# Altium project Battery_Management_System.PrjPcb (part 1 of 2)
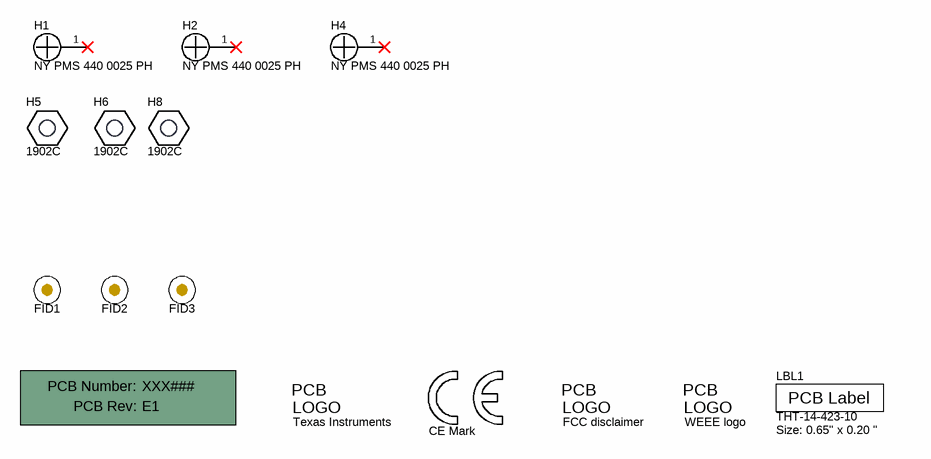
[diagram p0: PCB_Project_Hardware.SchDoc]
CopyrightYear: 2018; PCB_Layout: Who did the Layout?; PCB_Rev: E1; PRJ_Customer: Public Release; PRJ_Engineer: Enter name of project lead; PRJ_Number: XXX###; PRJ_Title: Change in menu Project|Project Options|Parameters; SCH_Rev: E1; TechSupport: http://www.ti.com/support; TID: N/A
8 sheets, 426 parts. Net scope: flat (ports and power ports of the same name join across sheets).
Board file: BMS Layout.PcbDoc
Sheets:
  PCB_Project_Hardware.SchDoc
  Block_Diagram.SchDoc
  Batt_Stack_Control (NMOS).SchDoc
  Power Tree.SchDoc
  MCU_ADC.SchDoc
  Balancer.SchDoc
  Temp Sensing.SchDoc
  Monitor.SchDoc

## Sheet PCB_Project_Hardware.SchDoc
size 431 x 279 mm; Date: Not shown in title block; ApprovedBy: Not shown in title block; CheckedBy: Not shown in title block; Author: Not shown in title block; CompanyName: Not shown in title block; Engineer: Not shown in title block; Organization: Not shown in title block; Address1: Not shown in title block; Address2: Not shown in title block; Address3: Not shown in title block; Address4: Not shown in title block; DocumentNumber: 3; Revision: Use project parameter SCH_Rev; SheetNumber: 1; SheetTotal: 8; PageSetup: Record=PageOptions¦CenterHorizontal=True¦CenterVertical=True¦PrintScale=1.00¦XCorrection=1.00¦YCorrection=1.00¦PrintKind=0¦BorderSize=5000000¦LeftOffset=0¦BottomOffset=0¦Orientation=2¦PaperLength=1000¦PaperWidth=1000¦Scale=100¦PaperSource=15¦PrintQuality=600¦MediaType=1¦DitherType=10¦PaperKind=Letter¦PrintScaleMode=1

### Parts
!PCB1  Printed Circuit Board  (value not drawn)  (mechanical)
FID1  Fiducial  [Fiducial10-20]  (value not drawn)
FID2  Fiducial  [Fiducial10-20]  (value not drawn)
FID3  Fiducial  [Fiducial10-20]  (value not drawn)
H1  NY PMS 440 0025 PH  [NY PMS 440 0025 PH]
H2  NY PMS 440 0025 PH  [NY PMS 440 0025 PH]
H4  NY PMS 440 0025 PH  [NY PMS 440 0025 PH]
H5  1902C  [Keystone_1902C]
H6  1902C  [Keystone_1902C]
H8  1902C  [Keystone_1902C]
LBL1  THT-14-423-10  Note: Size: 0.65" x 0.20 "  [Label_650x200]
Logo1  CE Mark  [CE_Mark_5mm]  (no BOM)
Logo2  Texas Instruments  [TI_Symbol_Overlay_Small]  (no BOM)
Logo3  FCC disclaimer  [FCC_disclaimer]  (no BOM)
Logo4  WEEE logo  [WEEE_Minimum]  (no BOM)

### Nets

Not connected (* = marked no-connect by the designer): H1 1*; H2 1*; H4 1*

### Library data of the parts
!PCB1 = CMP-0003618-2: Manufacturer: Any; PartNumber: XXX###
FID1-FID3 = CMP-0077181-1: Fiducial mark.  There is nothing to buy or mount.
H1 H2 H4 = CMP-0003617-1: Machine Screw, Round, #4-40 x 1/4, Nylon, Philips panhead; Manufacturer: B&F Fastener Supply; CompType: Hardware
H5 H6 H8 = CMP-0003610-1: Standoff, Hex, 0.5"L #4-40 Nylon; Manufacturer: Keystone; CompType: Hardware
LBL1 = CMP-0003625-1: Thermal Transfer Printable Labels, 0.650" W x 0.200" H - 10,000 per roll; Manufacturer: Brady; CompType: Label
Logo1 = CMP-0074844-1: SymbolCreator: a0412235
Logo2 = CMP-0074838-1: Texas Instrument Corporate Signature; SymbolCreator: a0412235; Lib Reference: TI_Logo; Library Reference: Logo
Logo3 = CMP-0074847-1: FCC_disclaimer; Library Reference: Logo
Logo4 = CMP-0074769-1

## Sheet Block_Diagram.SchDoc
size 431 x 279 mm; Date: Not shown in title block; ApprovedBy: Not shown in title block; CheckedBy: Not shown in title block; Author: Not shown in title block; CompanyName: Not shown in title block; Engineer: Not shown in title block; Organization: Not shown in title block; Address1: Not shown in title block; Address2: Not shown in title block; Address3: Not shown in title block; Address4: Not shown in title block; DocumentNumber: 2; Revision: Use project parameter SCH_Rev; SheetNumber: 2; SheetTotal: 8; PageSetup: Record=PageOptions¦CenterHorizontal=True¦CenterVertical=True¦PrintScale=1.00¦XCorrection=1.00¦YCorrection=1.00¦PrintKind=0¦BorderSize=5000000¦LeftOffset=0¦BottomOffset=0¦Orientation=2¦PaperLength=1000¦PaperWidth=1000¦Scale=100¦PaperSource=15¦PrintQuality=600¦MediaType=1¦DitherType=10¦PaperKind=Letter¦PrintScaleMode=1
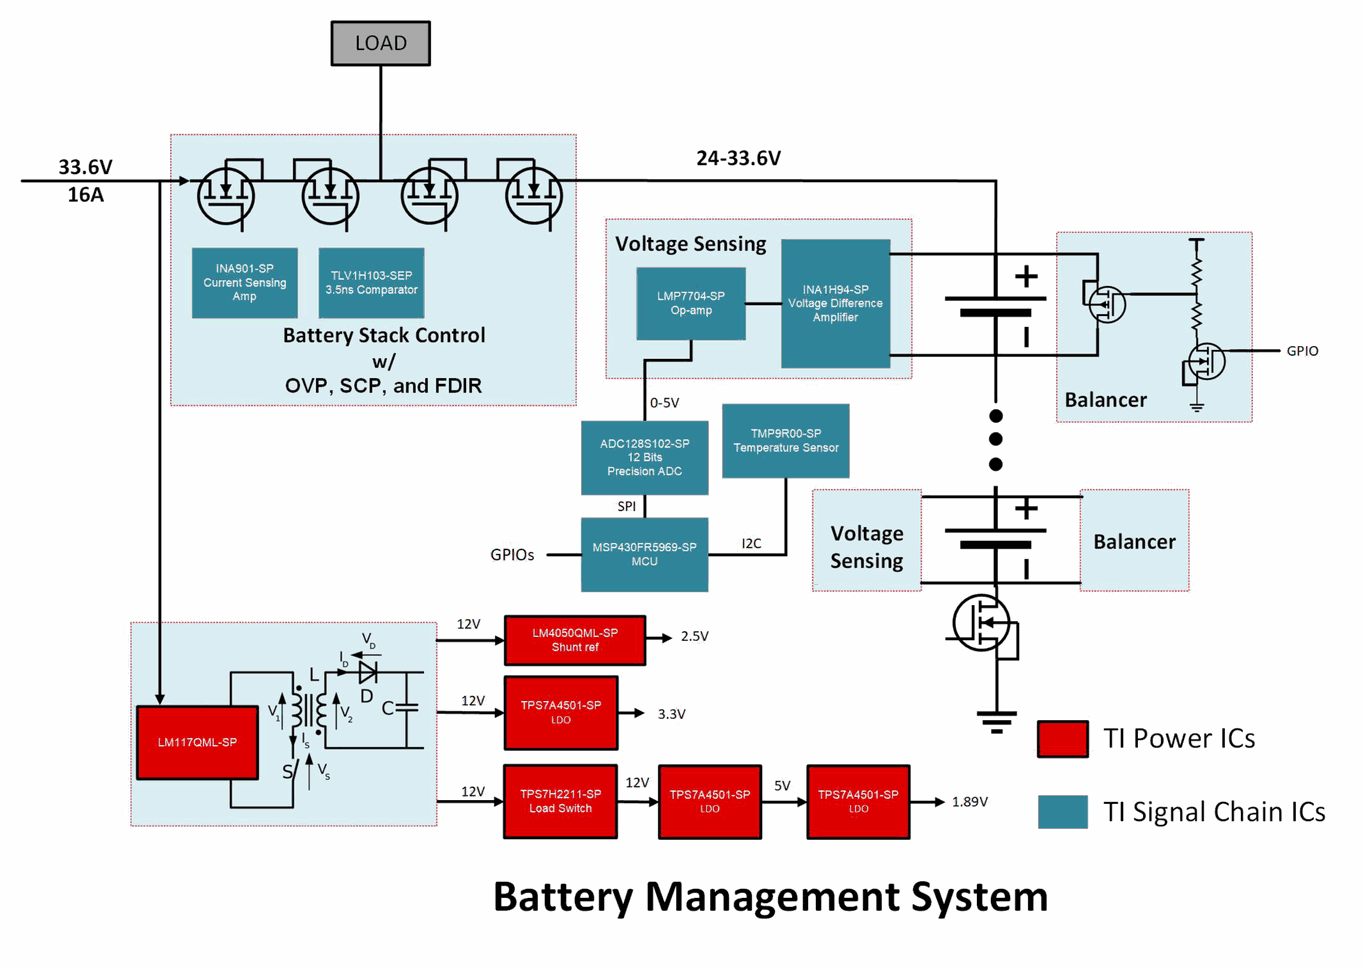
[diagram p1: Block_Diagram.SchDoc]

## Sheet Batt_Stack_Control (NMOS).SchDoc
size A2; Date: Not shown in title block; ApprovedBy: Not shown in title block; CheckedBy: Not shown in title block; Author: Not shown in title block; CompanyName: Not shown in title block; Engineer: Not shown in title block; Organization: Not shown in title block; Address1: Not shown in title block; Address2: Not shown in title block; Address3: Not shown in title block; Address4: Not shown in title block; DocumentNumber: 1; Revision: Use project parameter SCH_Rev; SheetNumber: 3; SheetTotal: 8; PageSetup: Record=PageOptions¦CenterHorizontal=True¦CenterVertical=True¦PrintScale=0.69¦XCorrection=1.00¦YCorrection=1.00¦PrintKind=0¦BorderSize=5000000¦LeftOffset=0¦BottomOffset=0¦Orientation=2¦PaperLength=1000¦PaperWidth=1000¦Scale=100¦PaperSource=15¦PrintQuality=600¦MediaType=1¦DitherType=10¦PaperKind=Letter¦PrintScaleMode=1
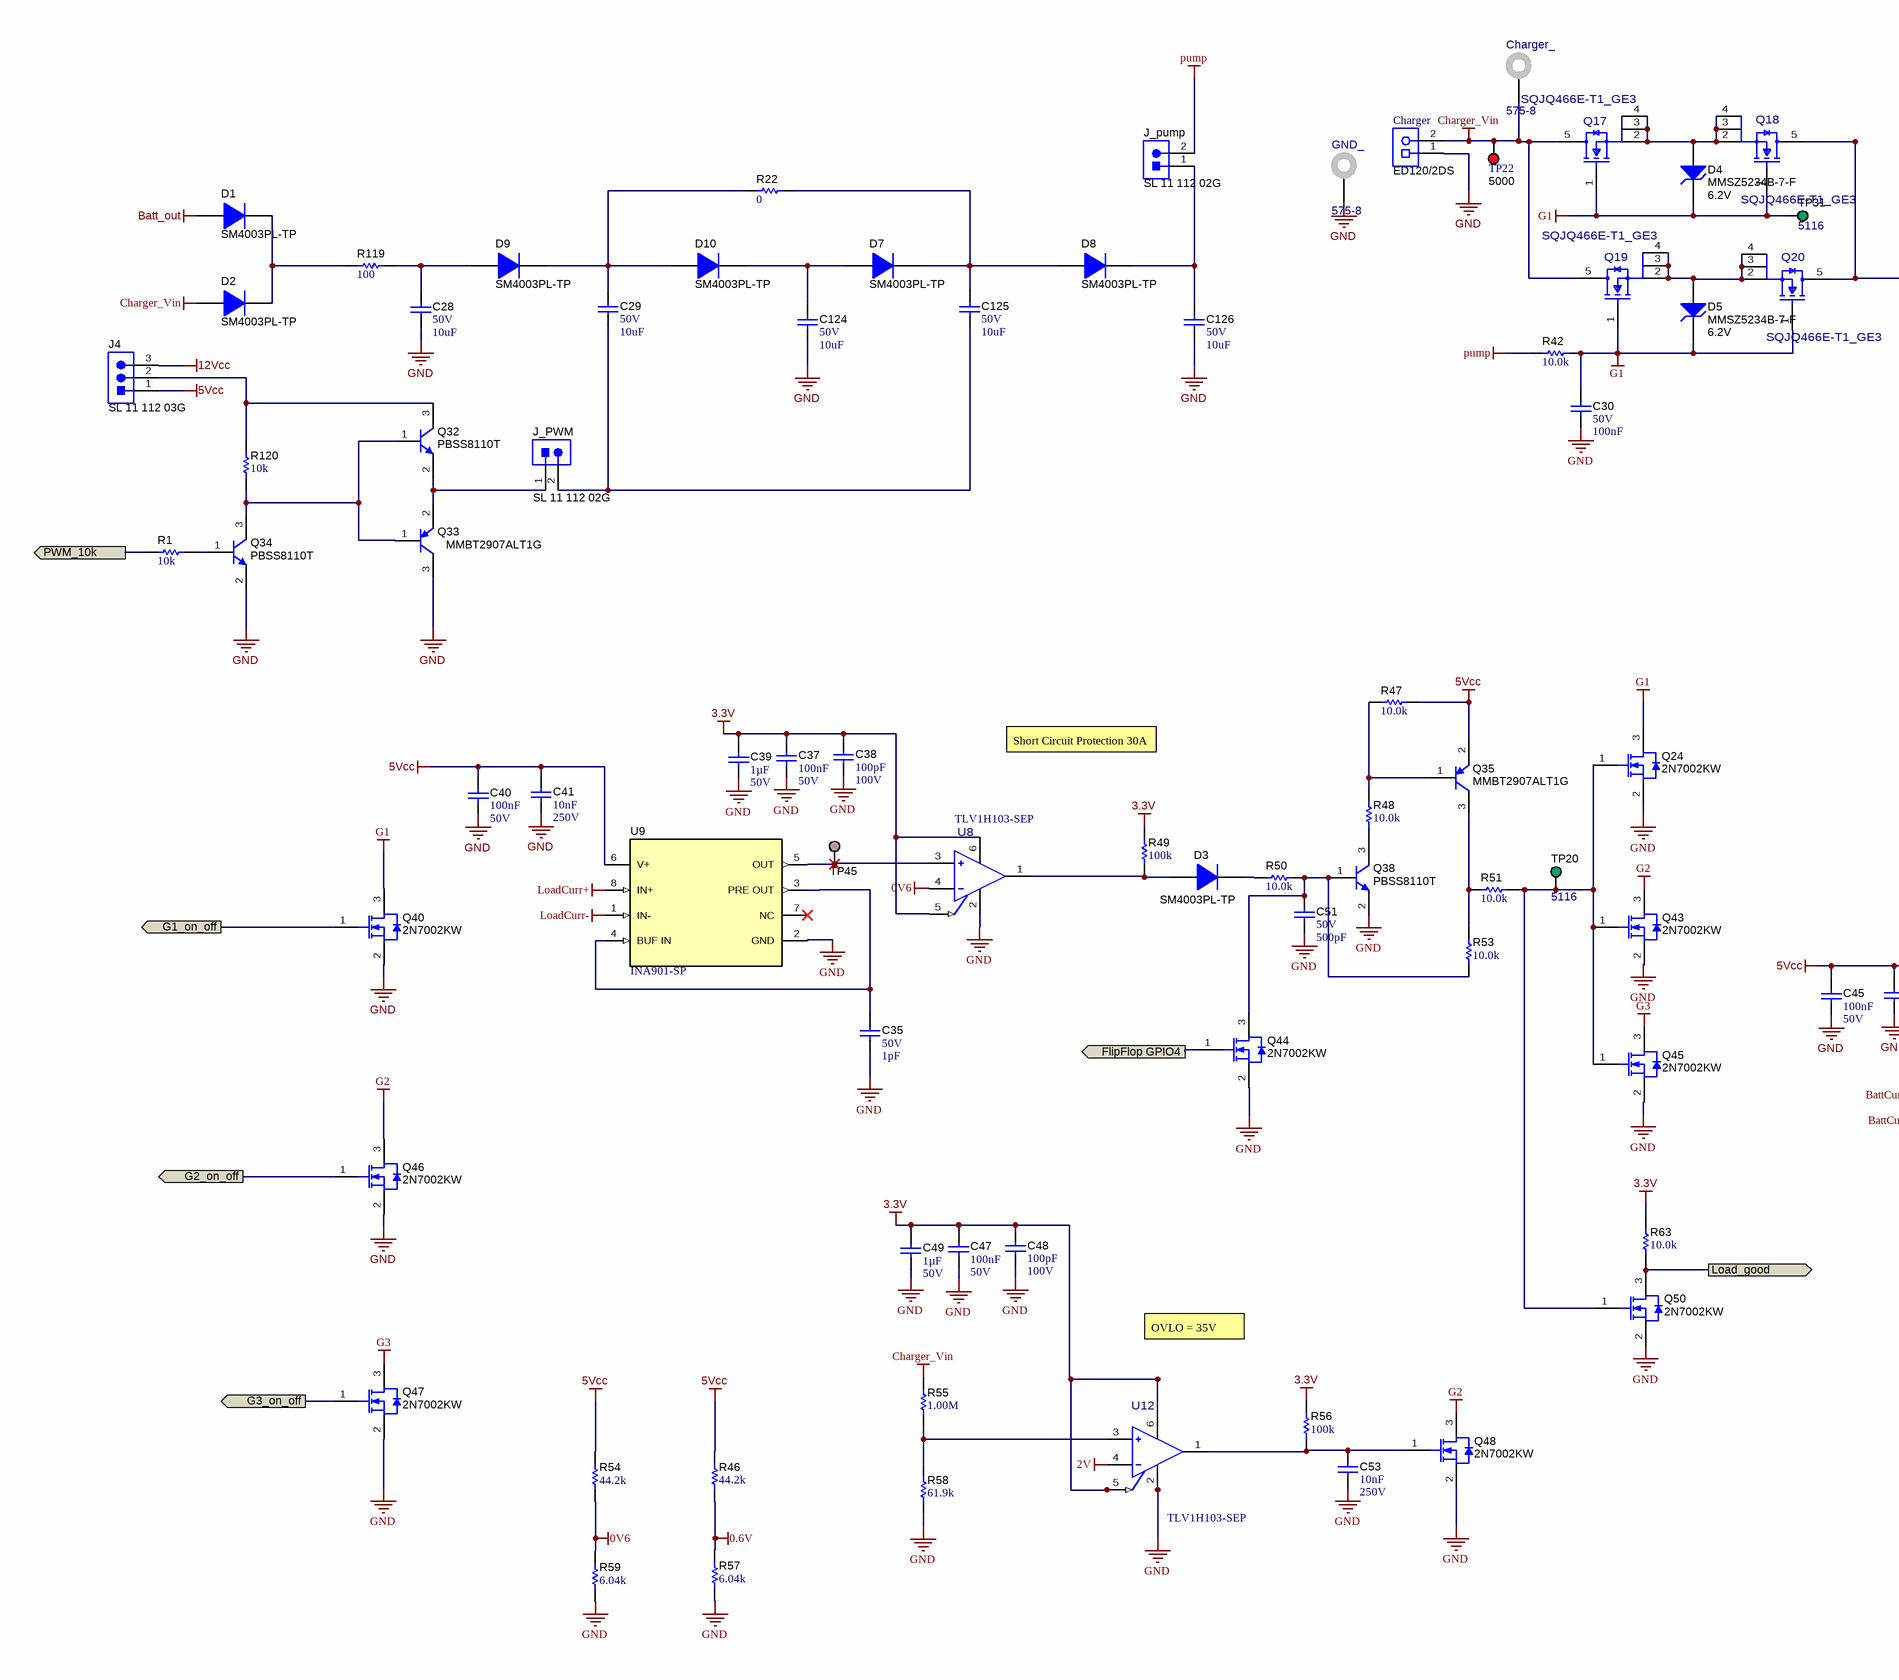
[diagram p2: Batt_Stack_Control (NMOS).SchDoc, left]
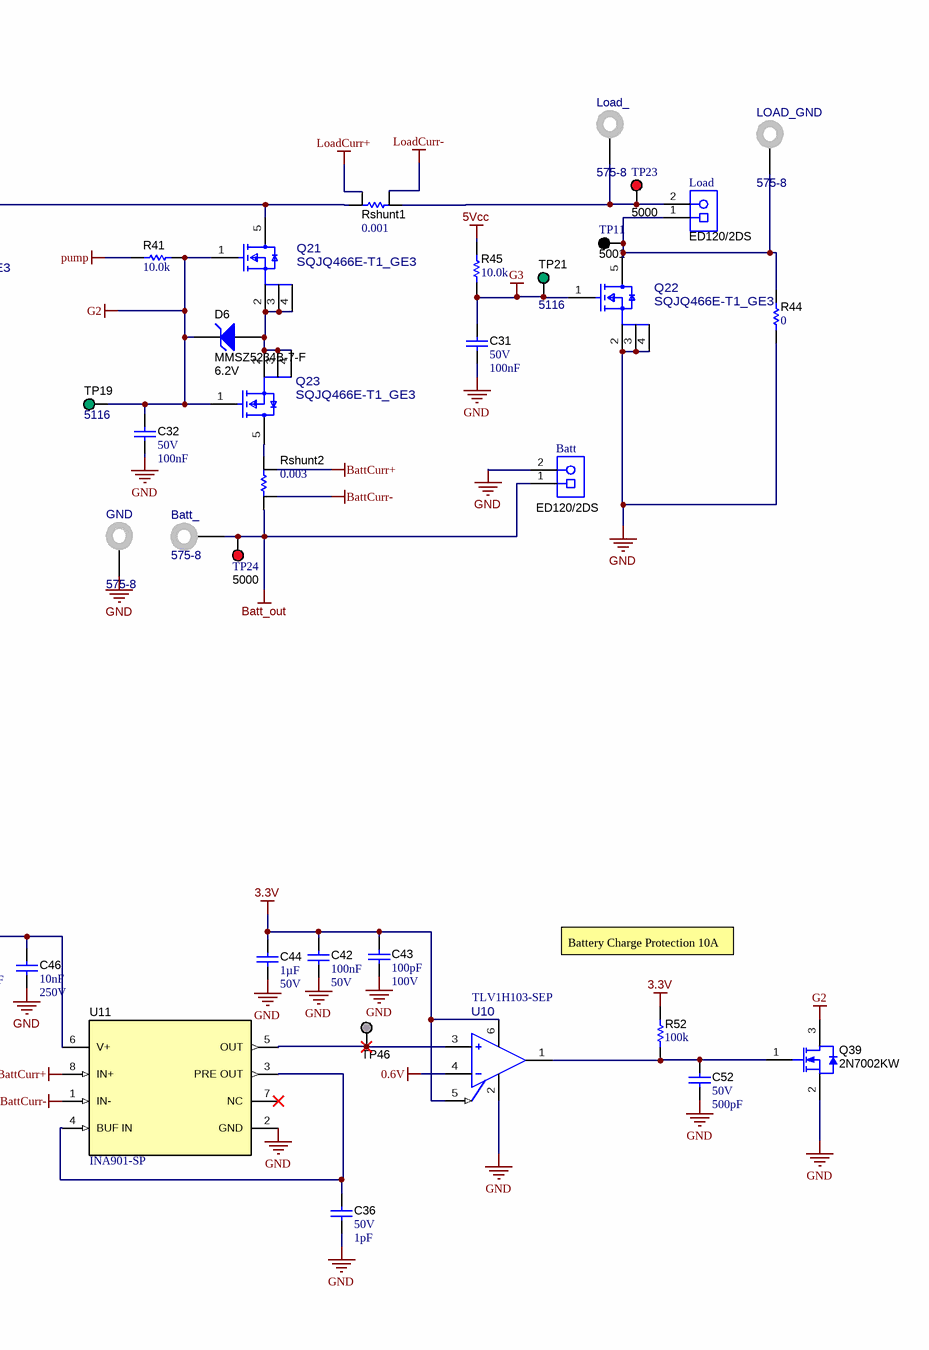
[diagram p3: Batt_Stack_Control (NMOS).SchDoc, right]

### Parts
Batt  ED120/2DS  [On-Shore_ED120_2DS]
Batt_  575-8  [Keystone575-8]
C28  VDC_V: 50V  ValueDisplayed: 10uF  [1210_280]  (hidden comment: CGA6P3X7S1H106K250AB)
C29  VDC_V: 50V  ValueDisplayed: 10uF  [1210_280]  (hidden comment: CGA6P3X7S1H106K250AB)
C30  VDC_V: 50V  Cap_F: 100nF  [0805_HV]  (hidden comment: 08055C104KAT2A)
C31  VDC_V: 50V  Cap_F: 100nF  [0805_HV]  (hidden comment: 08055C104KAT2A)
C32  VDC_V: 50V  Cap_F: 100nF  [0805_HV]  (hidden comment: 08055C104KAT2A)
C35  VDC_V: 50V  ValueDisplayed: 1pF  [0805_HV]  (hidden comment: CC0805CRNP09BN1R0)
C36  VDC_V: 50V  ValueDisplayed: 1pF  [0805_HV]  (hidden comment: CC0805CRNP09BN1R0)
C37  Cap_F: 100nF  VDC_V: 50V  [0805_HV]  (hidden comment: GCM21BR71H104KA37K)
C38  Cap_F: 100pF  VDC_V: 100V  [0805_HV]  (hidden comment: C0805C101J1RACTU)
C39  Cap_F: 1µF  VDC_V: 50V  [0805_HV]  (hidden comment: GCJ21BR71H105MA01L)
C40  Cap_F: 100nF  VDC_V: 50V  [0805_HV]  (hidden comment: GCM21BR71H104KA37K)
C41  Cap_F: 10nF  VDC_V: 250V  [0805_HV]  (hidden comment: QMK212B7103KG-T)
C42  Cap_F: 100nF  VDC_V: 50V  [0805_HV]  (hidden comment: GCM21BR71H104KA37K)
C43  Cap_F: 100pF  VDC_V: 100V  [0805_HV]  (hidden comment: C0805C101J1RACTU)
C44  Cap_F: 1µF  VDC_V: 50V  [0805_HV]  (hidden comment: GCJ21BR71H105MA01L)
C45  Cap_F: 100nF  VDC_V: 50V  [0805_HV]  (hidden comment: GCM21BR71H104KA37K)
C46  Cap_F: 10nF  VDC_V: 250V  [0805_HV]  (hidden comment: QMK212B7103KG-T)
C47  Cap_F: 100nF  VDC_V: 50V  [0805_HV]  (hidden comment: GCM21BR71H104KA37K)
C48  Cap_F: 100pF  VDC_V: 100V  [0805_HV]  (hidden comment: C0805C101J1RACTU)
C49  Cap_F: 1µF  VDC_V: 50V  [0805_HV]  (hidden comment: GCJ21BR71H105MA01L)
C51  VDC_V: 50V  ValueDisplayed: 500pF  [0805_HV]  (hidden comment: 08055A501GAT2A)
C52  VDC_V: 50V  ValueDisplayed: 500pF  [0805_HV]  (hidden comment: 08055A501GAT2A)
C53  Cap_F: 10nF  VDC_V: 250V  [0805_HV]  (hidden comment: QMK212B7103KG-T)
C124  VDC_V: 50V  ValueDisplayed: 10uF  [1210_280]  (hidden comment: CGA6P3X7S1H106K250AB)
C125  VDC_V: 50V  ValueDisplayed: 10uF  [1210_280]  (hidden comment: CGA6P3X7S1H106K250AB)
C126  VDC_V: 50V  ValueDisplayed: 10uF  [1210_280]  (hidden comment: CGA6P3X7S1H106K250AB)
Charger  ED120/2DS  [On-Shore_ED120_2DS]
Charger_  575-8  [Keystone575-8]
D1  SM4003PL-TP  [SOD-123FL]
D2  SM4003PL-TP  [SOD-123FL]
D3  SM4003PL-TP  [SOD-123FL]
D4  MMSZ5234B-7-F  value 6.2V  [SOD-123]
D5  MMSZ5234B-7-F  value 6.2V  [SOD-123]
D6  MMSZ5234B-7-F  value 6.2V  [SOD-123]
D7  SM4003PL-TP  [SOD-123FL]
D8  SM4003PL-TP  [SOD-123FL]
D9  SM4003PL-TP  [SOD-123FL]
D10  SM4003PL-TP  [SOD-123FL]
GND  575-8  [Keystone575-8]
GND_  575-8  [Keystone575-8]
J4  SL 11 112 03G  [Fischer_SL-11-112-03G]
J_pump  SL 11 112 02G  [Fischer_SL-11-112-02G]
J_PWM  SL 11 112 02G  [Fischer_SL-11-112-02G]
Load  ED120/2DS  [On-Shore_ED120_2DS]
Load_  575-8  [Keystone575-8]
LOAD_GND  575-8  [Keystone575-8]
Q17  SQJQ466E-T1_GE3  [FP-SQJQ466E-T1_GE3_PowerPAK 8 x 8L-MFG]
Q18  SQJQ466E-T1_GE3  [FP-SQJQ466E-T1_GE3_PowerPAK 8 x 8L-MFG]
Q19  SQJQ466E-T1_GE3  [FP-SQJQ466E-T1_GE3_PowerPAK 8 x 8L-MFG]
Q20  SQJQ466E-T1_GE3  [FP-SQJQ466E-T1_GE3_PowerPAK 8 x 8L-MFG]
Q21  SQJQ466E-T1_GE3  [FP-SQJQ466E-T1_GE3_PowerPAK 8 x 8L-MFG]
Q22  SQJQ466E-T1_GE3  [FP-SQJQ466E-T1_GE3_PowerPAK 8 x 8L-MFG]
Q23  SQJQ466E-T1_GE3  [FP-SQJQ466E-T1_GE3_PowerPAK 8 x 8L-MFG]
Q24  2N7002KW  [SOT-323]
Q32  PBSS8110T  [SOT-23]
Q33  MMBT2907ALT1G  [SOT-23]
Q34  PBSS8110T  [SOT-23]
Q35  MMBT2907ALT1G  [SOT-23]
Q38  PBSS8110T  [SOT-23]
Q39  2N7002KW  [SOT-323]
Q40  2N7002KW  [SOT-323]
Q43  2N7002KW  [SOT-323]
Q44  2N7002KW  [SOT-323]
Q45  2N7002KW  [SOT-323]
Q46  2N7002KW  [SOT-323]
Q47  2N7002KW  [SOT-323]
Q48  2N7002KW  [SOT-323]
Q50  2N7002KW  [SOT-323]
R1  ValueDisplayed: 10k  [0805_HV]  (hidden comment: ERJ-6GEYJ103V)
R22  ValueDisplayed: 0  [0805_HV]  (hidden comment: MCR10EZHJ000)
R41  ValueDisplayed: 10.0k  [0805_HV]  (hidden comment: CRCW080510K0FKEA)
R42  ValueDisplayed: 10.0k  [0805_HV]  (hidden comment: CRCW080510K0FKEA)
R44  ValueDisplayed: 0  [2512]  (hidden comment: 3522ZR)
R45  ValueDisplayed: 10.0k  [0805_HV]  (hidden comment: CRCW080510K0FKEA)
R46  ValueDisplayed: 44.2k  [0805_HV]  (hidden comment: RT0805BRD0744K2L)
R47  ValueDisplayed: 10.0k  [0805_HV]  (hidden comment: CRCW080510K0FKEA)
R48  ValueDisplayed: 10.0k  [0805_HV]  (hidden comment: CRCW080510K0FKEA)
R49  ValueDisplayed: 100k  [0805_HV]  (hidden comment: RG2012P-104-B-T5)
R50  ValueDisplayed: 10.0k  [0805_HV]  (hidden comment: CRCW080510K0FKEA)
R51  ValueDisplayed: 10.0k  [0805_HV]  (hidden comment: CRCW080510K0FKEA)
R52  ValueDisplayed: 100k  [0805_HV]  (hidden comment: RG2012P-104-B-T5)
R53  ValueDisplayed: 10.0k  [0805_HV]  (hidden comment: CRCW080510K0FKEA)
R54  ValueDisplayed: 44.2k  [0805_HV]  (hidden comment: RT0805BRD0744K2L)
R55  ValueDisplayed: 1.00M  [1206]  (hidden comment: RC1206FR-071ML)
R56  ValueDisplayed: 100k  [0805_HV]  (hidden comment: RG2012P-104-B-T5)
R57  ValueDisplayed: 6.04k  [0805_HV]  (hidden comment: RT0805BRD076K04L)
R58  ValueDisplayed: 61.9k  [1206]  (hidden comment: ERJ-8ENF6192V)
R59  ValueDisplayed: 6.04k  [0805_HV]  (hidden comment: RT0805BRD076K04L)
R63  ValueDisplayed: 10.0k  [0805_HV]  (hidden comment: CRCW080510K0FKEA)
R119  ValueDisplayed: 100  [0805_HV]  (hidden comment: CRCW0805100RJNEA)
R120  ValueDisplayed: 10k  [0805_HV]  (hidden comment: ERJ-6GEYJ103V)
Rshunt1  ValueDisplayed: 0.001  [WSL3637_0.001]  (hidden comment: WSL36371L000FEA)
Rshunt2  ValueDisplayed: 0.003  [WSL3637_0_002]  (hidden comment: WSL36373L000FEA)
TP11  5001  [Keystone5001]
TP19  5116  [Keystone_5116]
TP20  5116  [Keystone_5116]
TP21  5116  [Keystone_5116]
TP22  5000  [Keystone5000]
TP23  5000  [Keystone5000]
TP24  5000  [Keystone5000]
TP31  5116  [Keystone_5116]
TP45  TP_SM_1MM  [TP_SM_1MM]  (value not drawn)
TP46  TP_SM_1MM  [TP_SM_1MM]  (value not drawn)
U8  PartNumber: TLV1H103-SEP  [DBV0006A-MFG]  (hidden comment: TLV1H103MDBVTSEP)
U9  PartNumber: INA901-SP  [HKX0008A_Custom_A]  (hidden comment: INA901HKX/EM)
U10  PartNumber: TLV1H103-SEP  [DBV0006A-MFG]  (hidden comment: TLV1H103MDBVTSEP)
U11  PartNumber: INA901-SP  [HKX0008A_Custom_A]  (hidden comment: INA901HKX/EM)
U12  PartNumber: TLV1H103-SEP  [DBV0006A-MFG]  (hidden comment: TLV1H103MDBVTSEP)

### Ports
FlipFlop GPIO4 (out), G1_on_off (out), G2_on_off (out), G3_on_off (out), Load_good (out), PWM_10k (out)

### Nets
0.6V: R46.1 R57.2 U10.4(IN-)
0V6: R54.1 R59.2 U8.4(IN-)
2V: U12.4(IN-)
3.3V: C37.1 C38.1 C39.1 C42.1 C43.1 C44.1 C47.1 C48.1 C49.1 R49.2 R52.2 R56.2 R63.2 U8.5(~{LE}/HYST) U8.6(VCC) U10.5(~{LE}/HYST) U10.6(VCC) U12.5(~{LE}/HYST) U12.6(VCC)
5Vcc: C40.1 C41.1 C45.1 C46.1 J4.1 Q35.2(E) R45.2 R46.2 R47.2 R54.2 U9.6(V+) U11.6(V+)
12Vcc: J4.3
Batt_out: Batt.1 Batt_.1 D1.2(A) Rshunt2.2 TP24.1
BattCurr+: Rshunt2.3 U11.8(IN+)
BattCurr-: Rshunt2.4 U11.1(IN-)
Charger_Vin: Charger.2 Charger_.1 D2.2(A) Q17.5(D) Q19.5(D) R55.2 TP22.1
G1: C30.1 D4.1(K) D5.1(K) Q17.1(G) Q18.1(G) Q19.1(G) Q20.1(G) Q24.3(D) Q40.3(D) R42.2 TP31.1
G2: C32.1 D6.1(K) Q21.1(G) Q23.1(G) Q39.3(D) Q43.3(D) Q46.3(D) Q48.3(D) R41.2 TP19.1
G3: C31.1 Q22.1(G) Q45.3(D) Q47.3(D) R45.1 TP21.1
GND: Batt.2 C28.2 C30.2 C31.2 C32.2 C35.2 C36.2 C37.2 C38.2 C39.2 C40.2 C41.2 C42.2 C43.2 C44.2 C45.2 C46.2 C47.2 C48.2 C49.2 C51.2 C52.2 C53.2 C124.2 C126.2 Charger.1 GND.1 GND_.1 Q22.2(S) Q22.3(S) Q22.4(S) Q24.2(S) Q33.3(C) Q34.2(E) Q38.2(E) Q39.2(S) Q40.2(S) Q43.2(S) Q44.2(S) Q45.2(S) Q46.2(S) Q47.2(S) Q48.2(S) Q50.2(S) R44.1 R57.1 R58.1 R59.1 U8.2(VEE) U9.2(GND) U10.2(VEE) U11.2(GND) U12.2(VEE)
LoadCurr+: Rshunt1.3 U9.8(IN+)
LoadCurr-: Rshunt1.4 U9.1(IN-)
pump: J_pump.2 R41.1 R42.1
FlipFlop GPIO4: Q44.1(G) ; port FlipFlop GPIO4
G1_on_off: Q40.1(G) ; port G1_on_off
G2_on_off: Q46.1(G) ; port G2_on_off
G3_on_off: Q47.1(G) ; port G3_on_off
Load_good: Q50.3(D) R63.1 ; port Load_good
PWM_10k: R1.2 ; port PWM_10k
NetC28_1: C28.1 D9.2(A) R119.2
NetC29_1: C29.1 D9.1(K) D10.2(A) R22.2
NetC29_2: C29.2 C125.2 J_PWM.2
NetC35_1: C35.1 U9.3(PRE_OUT) U9.4(BUF_IN)
NetC36_1: C36.1 U11.3(PRE_OUT) U11.4(BUF_IN)
NetC51_1: C51.1 Q38.1(B) Q44.3(D) R50.2 R53.1
NetC52_1: C52.1 Q39.1(G) R52.1 U10.1(OUT)
NetC53_1: C53.1 Q48.1(G) R56.1 U12.1(OUT)
NetC124_1: C124.1 D7.2(A) D10.1(K)
NetC125_1: C125.1 D7.1(K) D8.2(A) R22.1
NetC126_1: C126.1 D8.1(K) J_pump.1
NetD1_1: D1.1(K) D2.1(K) R119.1
NetD3_1: D3.1(K) R50.1
NetD3_2: D3.2(A) R49.1 U8.1(OUT)
NetD4_2: D4.2(A) Q17.2(S) Q17.3(S) Q17.4(S) Q18.2(S) Q18.3(S) Q18.4(S)
NetD5_2: D5.2(A) Q19.2(S) Q19.3(S) Q19.4(S) Q20.2(S) Q20.3(S) Q20.4(S)
NetD6_2: D6.2(A) Q21.2(S) Q21.3(S) Q21.4(S) Q23.2(S) Q23.3(S) Q23.4(S)
NetJ4_2: J4.2 Q32.3(C) R120.2
NetJ_PWM_1: J_PWM.1 Q32.2(E) Q33.2(E)
NetLoad_1: Load.1 LOAD_GND.1 Q22.5(D) R44.2 TP11.1
NetLoad_2: Load.2 Load_.1 Rshunt1.2 TP23.1
NetQ18_5: Q18.5(D) Q20.5(D) Q21.5(D) Rshunt1.1
NetQ23_5: Q23.5(D) Rshunt2.1
NetQ24_1: Q24.1(G) Q43.1(G) Q45.1(G) Q50.1(G) R51.2 TP20.1
NetQ32_1: Q32.1(B) Q33.1(B) Q34.3(C) R120.1
NetQ34_1: Q34.1(B) R1.1
NetQ35_1: Q35.1(B) R47.1 R48.2
NetQ35_3: Q35.3(C) R51.1 R53.2
NetQ38_3: Q38.3(C) R48.1
NetR55_1: R55.1 R58.2 U12.3(IN+)
NetTP45_1: TP45.1 U8.3(IN+) U9.5(OUT)
NetTP46_1: TP46.1 U10.3(IN+) U11.5(OUT)

Not connected (* = marked no-connect by the designer): U9 7(NC)*; U11 7(NC)*

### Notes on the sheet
- Short Circuit Protection 30A
- Battery Charge Protection 10A
- OVLO = 35V

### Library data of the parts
Batt Charger Load = CMP-0074910-1: Terminal Block, 5.08 mm, 2x1, Brass, TH; Manufacturer: On-Shore Technology; Cert_VDE: Y; CNHeader: False; Current_A: 15A; Green_Lifecycle: Not Set; Shrouded: N; Gender: Female; Green_REACh: Incomplete; Voltage_V: 300V; Row_Count: 1; Pitch_mm: 5.08; CT: True
Batt_ Charger_ GND GND_ Load_ LOAD_GND = CMP-0055166-1: Standard Banana Jack, Uninsulated, 8.9mm; Manufacturer: Keystone; CT: TRUE; Green_REACh: Passed; CNHeader: FALSE; Green_Lifecycle: Active
C28 C29 C124-C126 = CMP-0009164-1: CAP, CERM, 10 uF, 50 V, +/- 10%, X7S, AEC-Q200 Grade 1, 1210; Manufacturer: TDK; TaMin_C: -55°C; ESR_ohm: 2.827m; Polarized: N; SizeAreaWB_mm2: 14.7; Value1: 0.002827 ohm; U/M: EA; Value: 10uF; TaMax_C: 125°C; SizeZ_mm: 2.8; SizeX_mm: 3.2; SizeY_mm: 2.5; SizeArea_mm2: 8; AEC Qualified: Y; Cap_F: 10µF; IRMS_A: 4.3729A; AEC Grade: 1; AEC Category: Q200
C30-C32 = CMP-0007632-2: CAP, CERM, 0.1 uF, 50 V, +/- 10%, X7R, 0805; Manufacturer: AVX; TaMin_C: -55°C; ESR_ohm: 0.024; Polarized: N; SizeAreaWB_mm2: 6.75; Value1: 0.024 ohm; U/M: EA; Value: 0.1uF; TaMax_C: 125°C; SizeZ_mm: 1.45; SizeX_mm: 2; SizeY_mm: 1.25; Cap_Case: 0805; SizeArea_mm2: 2.5; AEC Category: Q200
C35 C36 = CMP-0007900-2: CAP, CERM, 1 pF, 50 V, +/- 25%, C0G/NP0, 0805; Manufacturer: Yageo America; TaMin_C: -55°C; Polarized: N; SizeAreaWB_mm2: 6.75; Value1: Unknown; U/M: EA; Value: 1pF; TaMax_C: 125°C; SizeZ_mm: 1.45; SizeX_mm: 2; SizeY_mm: 1.25; Cap_Case: 0805; SizeArea_mm2: 2.5; AEC Category: Q200
C37 C40 C42 C45 C47 = CMP-0008021-2: CAP, CERM, 0.1 uF, 50 V, +/- 10%, X7R, AEC-Q200 Grade 1, 0805; Manufacturer: MuRata; TaMin_C: -55°C; Polarized: N; SizeAreaWB_mm2: 6.75; Value1: Unknown; U/M: EA; Value: 0.1uF; TaMax_C: 125°C; SizeZ_mm: 1.45; SizeX_mm: 2; SizeY_mm: 1.25; Cap_Case: 0805; SizeArea_mm2: 2.5; AEC Qualified: Y; AEC Grade: 1; AEC Category: Q200
C38 C43 C48 = CMP-0007706-2: CAP, CERM, 100 pF, 100 V, +/- 5%, X7R, 0805; Manufacturer: Kemet; TaMin_C: -55°C; Polarized: N; SizeAreaWB_mm2: 6.75; Value1: Unknown; U/M: EA; Value: 100pF; TaMax_C: 125°C; SizeZ_mm: 1.45; SizeX_mm: 2; SizeY_mm: 1.25; Cap_Case: 0805; SizeArea_mm2: 2.5; AEC Category: Q200
C39 C44 C49 = CMP-0080480-1: CAP, CERM, 1 µF, 50 V,+/- 20%, X7R, AEC-Q200 Grade 1, 0805; Manufacturer: MuRata; TaMin_C: -55°C; Polarized: N; SizeAreaWB_mm2: 6.75; U/M: EA; Value: 1uF; TaMax_C: 125°C; SizeZ_mm: 1.45; SizeX_mm: 2; SizeY_mm: 1.25; Cap_Case: 0805; SizeArea_mm2: 2.5; AEC Qualified: Y; AEC Grade: 1; AEC Category: Q200
C41 C46 C53 = CMP-0008408-2: CAP, CERM, 0.01 uF, 250 V, +/- 10%, X7R, 0805; Manufacturer: Taiyo Yuden; TaMin_C: -55°C; Polarized: N; SizeAreaWB_mm2: 6.75; Value1: Unknown; U/M: EA; Value: 0.01uF; TaMax_C: 125°C; SizeZ_mm: 1.45; SizeX_mm: 2; SizeY_mm: 1.25; Cap_Case: 0805; SizeArea_mm2: 2.5; AEC Category: Q200
C51 C52 = CMP-0080090-1: CAP, CERM, 500 pF, 50 V,+/- 2%, C0G/NP0, 0805; Manufacturer: AVX; SizeAreaWB_mm2: 6.75; SizeArea_mm2: 2.5; AEC Qualified: N; AEC Category: Q200; Value: 500pF; TaMax_C: 125°C; SizeZ_mm: 1.45; TaMin_C: -55°C; SizeY_mm: 1.25; U/M: EA; SizeX_mm: 2; Cap_Case: 0805
D1-D3 D7-D10 = CMP-0077083-2: Diode, Standard Recovery Rectifier, 200 V, 1 A, SOD-123FL; Manufacturer: Micro Commercial Components; Green_Lifecycle: Not Set; AEC Category: Q101; SizeArea_mm2: 5.94; Vr_V: 200V; SizeAreaWB_mm2: 12.19; SizeY_mm: 1.65; AEC Qualified: N; SizeZ_mm: 0.98; SizeX_mm: 3.6; Green_REACh: Incomplete; Vf_V: 1.1V; TJmax_C: 175°C; Value: 200V; Value1: 1A
D4-D6 = CMP-0005805-3: Diode, Zener, 6.2 V, 500 mW, SOD-123; Manufacturer: Diodes Inc.; SizeY_mm: 1.7; AEC Category: Q101; SizeAreaWB_mm2: 13.095; SizeZ_mm: 1.35; SizeArea_mm2: 6.545; RJA_CperW: 350; Power_W: 500mW; Value1: 0.5W; SizeX_mm: 3.85
J4 = CMP-0075048-1: Header, 2.54mm, 3x1, Gold, TH; Manufacturer: Fischer Elektronik; CT: False; CNHeader: True
J_pump J_PWM = CMP-0075049-1: Header, 2.54mm, 2x1, Gold, TH; Manufacturer: Fischer Elektronik; CT: False; CNHeader: True
Q17-Q23 = CMP-0093493-1: N-Channel 60 V 200A (Tc) 150W (Tc) Surface Mount PowerPAK® 8 x 8; Manufacturer: Vishay; AEC Qualified: Yes; QgTyp_nC: 135nC @ 10V; Rdson45_ohm: 1.7m; SizeZ_mm: 2.03mm; VdsMax_V: 1.2V; Vgs_V: 20V; ChMode: False; Pulse Drain Current: 500A; Rthja Max: 50°C/W; TJmax_C: +175°C; Typ Forward Diode Voltage: 0.82V; Input Capacitace At Vds: 8170pF @ 25V; Turn Off Delay Time: 47ns; Standoff Height: 0mm; Turn On Delay Time: 24ns; Number Of N Channels: 1; Drain To Source Breakdown Voltage: 60V; Threshold Vgs Min: 2.5V; Threshold Vgs Max: 3.5V; AEC Grade: Grade 0; Transconductance: 140S
Q24 Q39 Q40 Q43-Q48 Q50 = CMP-0000774-1: MOSFET, N-CH, 60 V, 0.31 A, SOT-323; Alternate Manufacturer: None; Manufacturer: Fairchild Semiconductor; SizeZ_mm: 1.1; ChType: N; Value1: 1; VdsMax_V: 60V; SizeX_mm: 2.2; Vgs_V: 2.1V; Value: 60V; Rdson45_ohm: 1.6; SizeArea_mm2: 4.84; AEC Category: Q101; IdsMax_A: 3.1dA; SizeAreaWB_mm2: 10.24; U/M: EA
Q32 Q34 Q38 = CMP-0000451-1: Transistor, NPN, 100 V, 1 A, SOT-23; Manufacturer: NXP Semiconductor; TaMax_C: 150°C; Value2: 500; Value1: 1 A; Vcesat1_V: 40mV; SizeX_mm: 2.5; SizeY_mm: 3; TaMin_C: -65°C; IcRated_A: 1A; CompType: BJT; SizeZ_mm: 1.1; Value: 100 V; SizeArea_mm2: 7.5; NPN: 1; Vceo_V: 100V; PNP: 0; AEC Category: Q101; SizeAreaWB_mm2: 14; U/M: EA
Q33 Q35 = CMP-0000344-1: Transistor, PNP, 60 V, 0.6 A, SOT-23; Manufacturer: ON Semiconductor; TaMax_C: 150°C; Value1: 0.6 A; Vcesat1_V: 1.6V; SizeX_mm: 2.5; SizeY_mm: 3; TaMin_C: -55°C; IcRated_A: 600mA; CompType: BJT; SizeZ_mm: 1.1; Value: 60 V; SizeArea_mm2: 7.5; NPN: 0; Vceo_V: 60V; PNP: 1; AEC Category: Q101; SizeAreaWB_mm2: 14; U/M: EA
R1 R120 = CMP-0020620-3: RES, 10 k, 5%, 0.125 W, AEC-Q200 Grade 0, 0805; Manufacturer: Panasonic; Power_W: 125mW; TempCo: 200 ppm/C; Value_Code: 10k0; Value: 10k; EIA_Code: E24; SizeX_mm: 2; SizeY_mm: 1.25; SizeZ_mm: 1.45; Value2: 0.125W; SizeArea_mm2: 2.5; AEC Qualified: Y; VDC_V: 150V; AEC Category: Q200; AEC Grade: 0; SizeAreaWB_mm2: 6.75
R22 = CMP-0020801-3: RES, 0, 5%, 0.125 W, 0805; Manufacturer: Rohm; SizeX_mm: 2; Value_Code: 0000; MFG_Status: TI_Obsolete; U/M: EA; SizeZ_mm: 1.45; Power_W: 125mW; Value: 0; TempCo: 400 ppm/C; SizeY_mm: 1.25; EIA_Code: E24; Value2: 0.125W; AEC Category: Q200; VDC_V: 150V; SizeArea_mm2: 2.5
R41 R42 R45 R47 R48 R50 R51 R53 R63 = CMP-0020842-3: RES, 10.0 k, 1%, 0.125 W, AEC-Q200 Grade 0, 0805; Manufacturer: Vishay-Dale; Power_W: 125mW; TempCo: 100 ppm/C; Value_Code: 10k0; Value: 10.0k; EIA_Code: E96; Res_ohm: 10k; SizeX_mm: 2; SizeY_mm: 1.25; SizeZ_mm: 1.45; Value2: 0.125W; SizeArea_mm2: 2.5; AEC Qualified: Y; VDC_V: 150V; AEC Category: Q200; AEC Grade: 0
R44 = CMP-0086260-1: RES, 0, 3 W, 2512; Manufacturer: TE Connectivity; SizeAreaWB_mm2: 43.16; Value: 0; SizeArea_mm2: 20.16; EIA_Code: E24; SizeZ_mm: 0.71; AEC Category: Q200; SizeX_mm: 6.3; Value_Code: 0000; Power_W: 3W; Tolerance_%: 0%; SizeY_mm: 3.2; AEC Qualified: N
R46 R54 = CMP-0020087-2: RES, 44.2 k, 0.1%, 0.125 W, 0805; Manufacturer: Yageo America; Power_W: 125mW; TempCo: 25 ppm/C; Value_Code: 44k2; U/M: EA; Value: 44.2k; EIA_Code: E192; SizeX_mm: 2; SizeY_mm: 1.25; SizeZ_mm: 1.45; Value2: 0.125W; SizeArea_mm2: 2.5; VDC_V: 150V; AEC Category: Q200
R49 R52 R56 = CMP-0018857-2: RES, 100 k, 0.1%, 0.125 W, 0805; Manufacturer: Susumu Co Ltd; Power_W: 125mW; TempCo: 25 ppm/C; U/M: EA; Value: 100k; EIA_Code: E192; SizeX_mm: 2; SizeY_mm: 1.25; SizeZ_mm: 1.45; Value2: 0.125W; SizeArea_mm2: 2.5; VDC_V: 100V; AEC Category: Q200
R55 = CMP-0018027-2: RES, 1.00 M, 1%, 0.25 W, 1206; Manufacturer: Yageo America; Power_W: 250mW; TempCo: 100 ppm/C; Value_Code: 1M00; U/M: EA; Value: 1.00Meg; EIA_Code: E96; Res_ohm: 1M; SizeX_mm: 3.2; SizeY_mm: 1.6; SizeZ_mm: 1.35; Value2: 0.25W; SizeArea_mm2: 5.12; VDC_V: 200V; AEC Category: Q200
R57 R59 = CMP-0020273-2: RES, 6.04 k, 0.1%, 0.125 W, 0805; Manufacturer: Yageo America; Power_W: 125mW; TempCo: 25 ppm/C; Value_Code: 6k04; U/M: EA; Value: 6.04k; EIA_Code: E192; SizeX_mm: 2; SizeY_mm: 1.25; SizeZ_mm: 1.45; Value2: 0.125W; SizeArea_mm2: 2.5; VDC_V: 150V; AEC Category: Q200
R58 = CMP-0017675-3: RES, 61.9 k, 1%, 0.25 W, AEC-Q200 Grade 0, 1206; Manufacturer: Panasonic; Power_W: 250mW; TempCo: 100 ppm/C; Value_Code: 61k9; Value: 61.9k; EIA_Code: E96; SizeX_mm: 3.2; SizeY_mm: 1.6; SizeZ_mm: 1.35; Value2: 0.25W; SizeArea_mm2: 5.12; AEC Qualified: Y; VDC_V: 200V; AEC Category: Q200; AEC Grade: 0; SizeAreaWB_mm2: 10.92
R119 = CMP-0020445-1: RES, 100, 5%, 0.125 W, 0805; Manufacturer: Vishay-Dale; Power_W: 125mW; TempCo: 200 ppm/C; Value_Code: 100R; U/M: EA; Value: 100; EIA_Code: E24; SizeX_mm: 2; SizeY_mm: 1.25; SizeZ_mm: 1.45; Value2: 0.125W; SizeArea_mm2: 2.5; VDC_V: 150V; AEC Category: Q200
Rshunt1 = CMP-0015291-2: RES, 0.001, 1%, 3 W, WSL3637; Manufacturer: Vishay-Dale; Power_W: 3W; TempCo: 75 ppm/C; Value_Code: 1L000; U/M: EA; Value: 0.001; EIA_Code: E96; Res_ohm: 1m; CompType: Resistor; VDC_V: 0V; AEC Category: Q200
Rshunt2 = CMP-0082607-1: RES, 0.003, 1%, 3 W, AEC-Q200 Grade 0, 9.14x9.4mm; Manufacturer: Vishay-Dale; Value_Code: 3L000; SizeAreaWB_mm2: 126.996; SizeArea_mm2: 85.916; AEC Qualified: Y; AEC Category: Q200; Res_ohm: 3m; Value: 0.003; SizeZ_mm: 0.889; EIA_Code: E96; TempCo: 50 ppm/C; AEC Grade: 0; Power_W: 3W; SizeY_mm: 9.4; CompType: Resistor; SizeX_mm: 9.14
TP11 = CMP-0055138-1: Test Point, Miniature, Black, TH; Manufacturer: Keystone; CNHeader: FALSE; Green_Lifecycle: Active; Green_REACh: Passed; ContactFinish: Silver; CT: TRUE
TP19-TP21 TP31 = CMP-0055164-1: Test Point, Miniature, Green, TH; Manufacturer: Keystone; CNHeader: FALSE; Green_Lifecycle: Active; Green_REACh: Passed; Row_Count: 1; ContactFinish: Silver; CT: TRUE; Cert_UL: Y
TP22-TP24 = CMP-0055137-1: Test Point, Miniature, Red, TH; Manufacturer: Keystone; CNHeader: FALSE; Green_Lifecycle: Active; Green_REACh: Passed; ContactFinish: Silver; CT: TRUE
TP45 TP46 = CMP-0003825-1: 1mm Test Point, SMT; Manufacturer: Any
U8 U10 U12 = CMP-0036814-1: Radiation-Tolerant High-Speed Comparator with 3.5ns Propagation Delay; Manufacturer: Texas Instruments; Min Supply Voltage: 2.4V; TJmax_C: +150°C; TaMax_C: +125°C; Output Current Per Channel: 30mA; Number Of Channels: 1; AEC Qualified: No; Input Bias Current: 1uA; SizeZ_mm: 1.45mm; Input Offset Voltage: 0.5mV; Standoff Height: 0mm; TaMin_C: -40°C; Max Supply Voltage: 5.5V; Nominal Supply Current: 5.7mA; Gain Bandwidth: 250MHz
U9 U11 = CMP-0081563-2: Voltage Output, Unidirectional Measurement Current-Shunt Monitor, HKX0008A (CFP-8); Manufacturer: Texas Instruments; SizeZ_mm: 2.8; Rating: Space; AEC Category: Q200; CompType: IC; AEC Qualified: N

## Sheet Power Tree.SchDoc
size 431 x 279 mm; Date: Not shown in title block; ApprovedBy: Not shown in title block; CheckedBy: Not shown in title block; Author: Not shown in title block; CompanyName: Not shown in title block; Engineer: Not shown in title block; Organization: Not shown in title block; Address1: Not shown in title block; Address2: Not shown in title block; Address3: Not shown in title block; Address4: Not shown in title block; DocumentNumber: 1; Revision: Use project parameter SCH_Rev; SheetNumber: 4; SheetTotal: 8; PageSetup: Record=PageOptions¦CenterHorizontal=True¦CenterVertical=True¦PrintScale=1.00¦XCorrection=1.00¦YCorrection=1.00¦PrintKind=0¦BorderSize=5000000¦LeftOffset=0¦BottomOffset=0¦Orientation=2¦PaperLength=1000¦PaperWidth=1000¦Scale=100¦PaperSource=15¦PrintQuality=600¦MediaType=1¦DitherType=10¦PaperKind=Letter¦PrintScaleMode=1
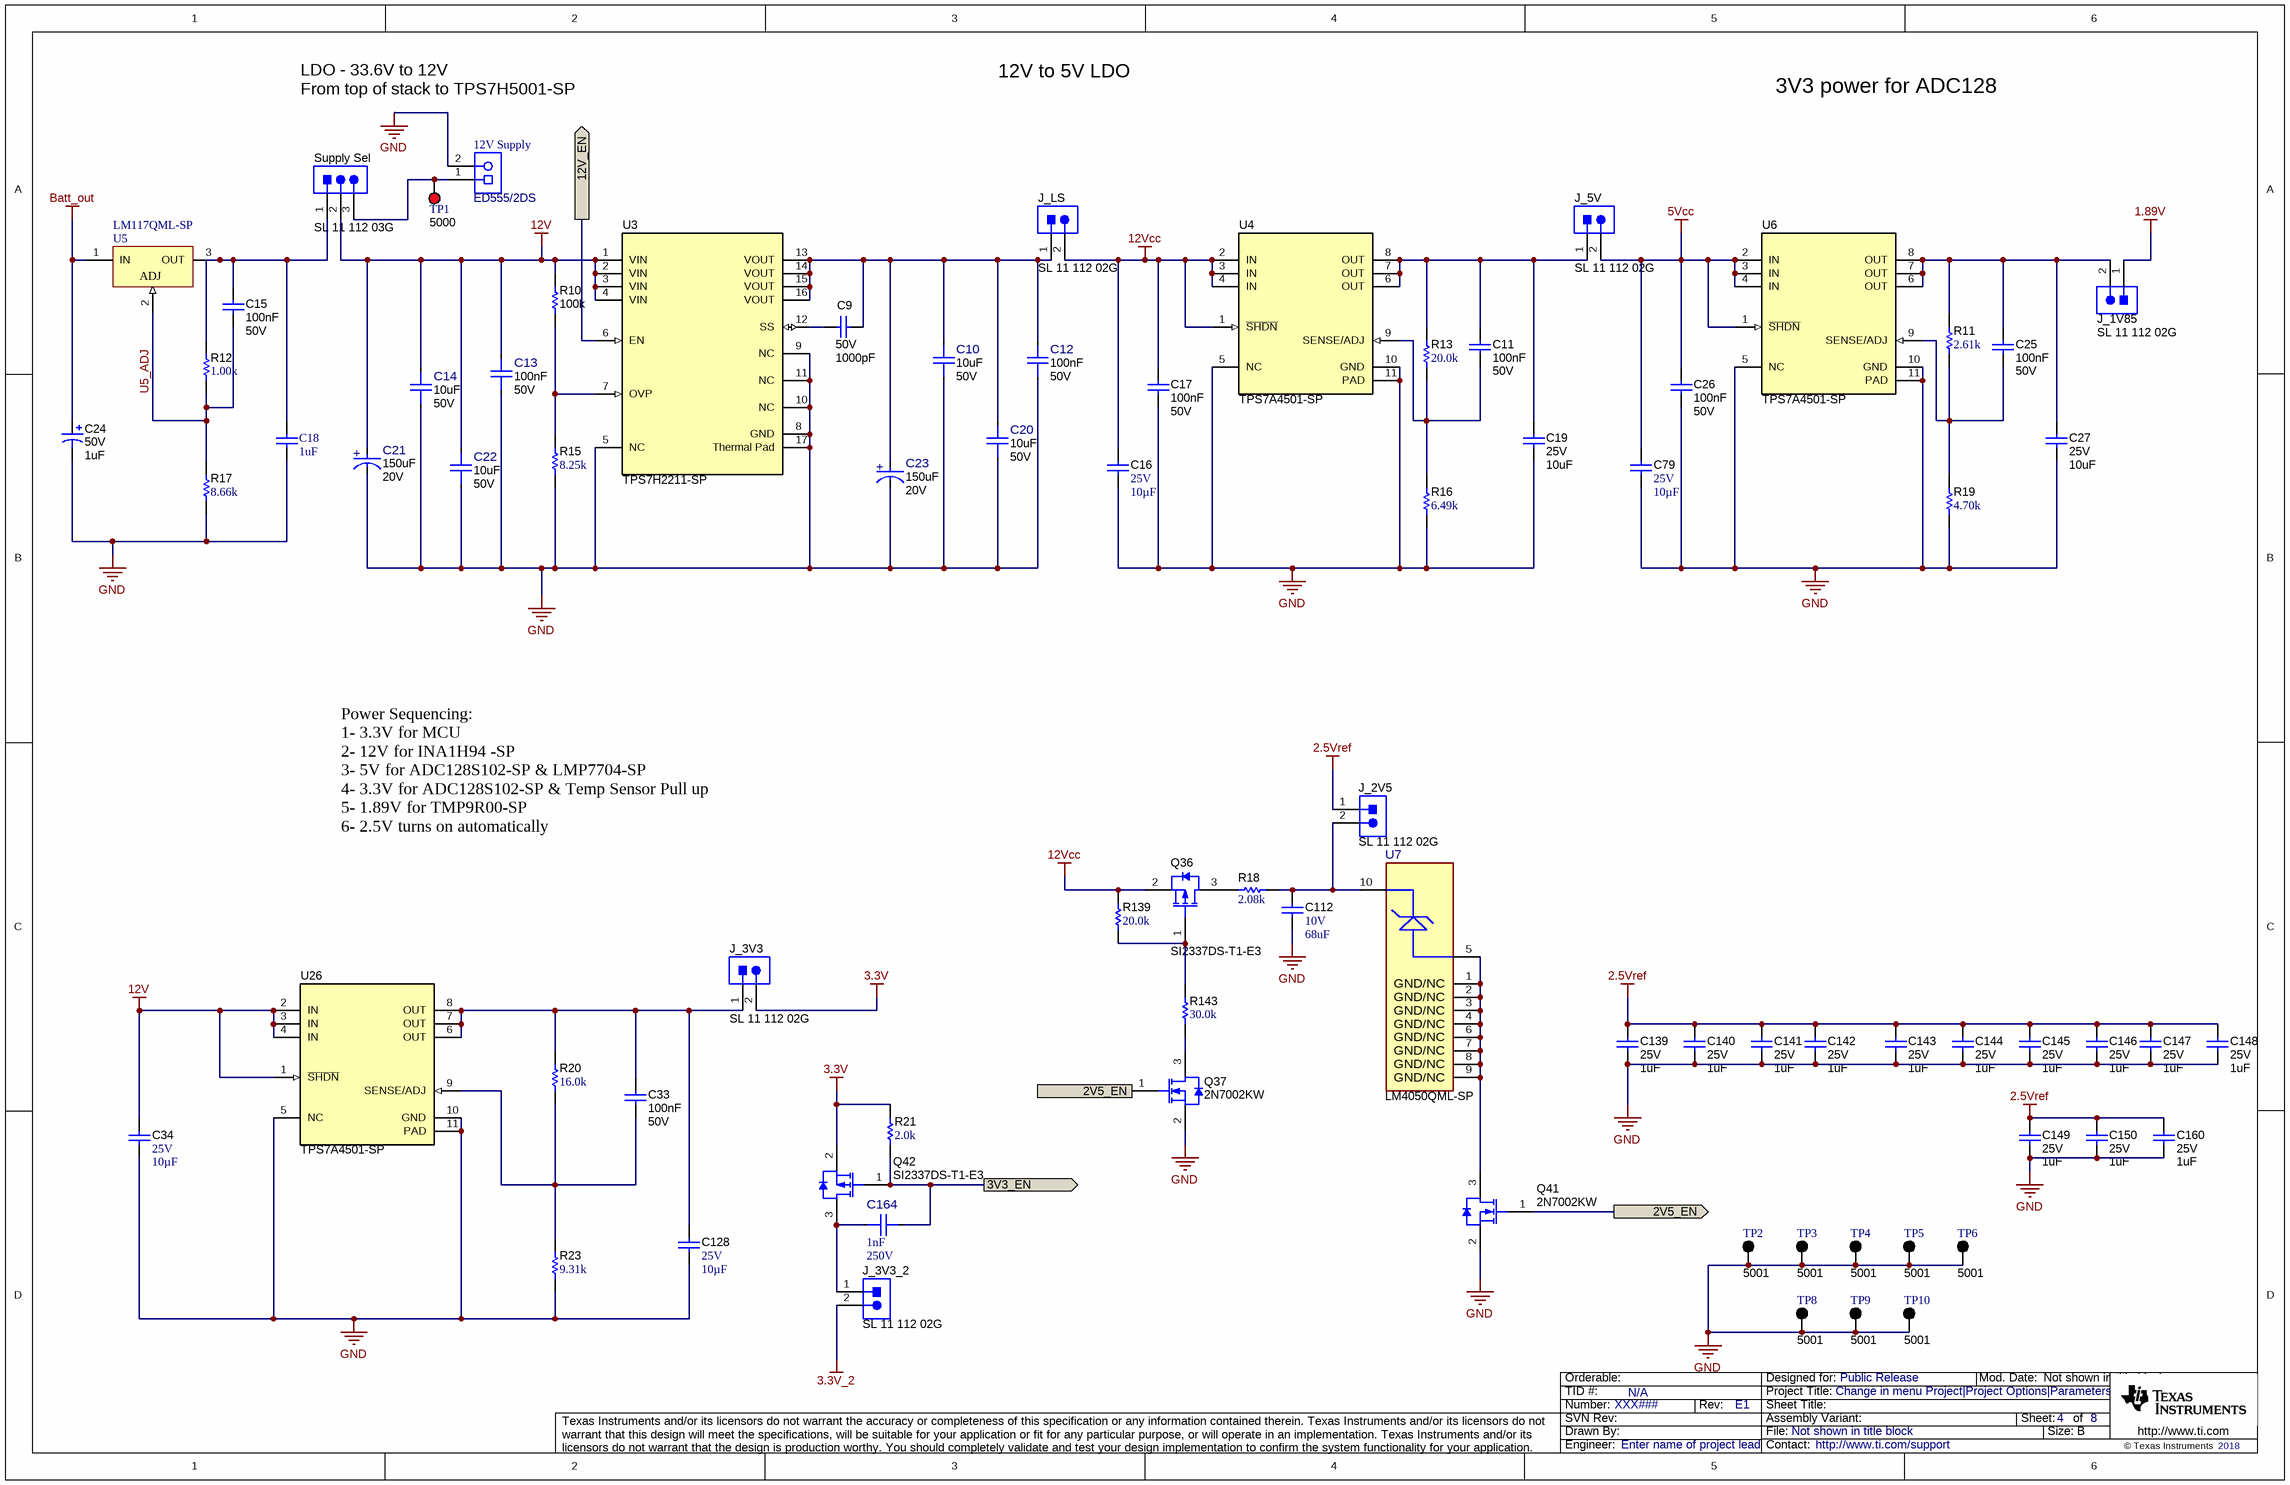
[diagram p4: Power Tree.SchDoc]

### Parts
12V_Supply  ED555/2DS  [TERM_BLK_ED555-2DS]
C9  VDC_V: 50V  ValueDisplayed: 1000pF  [0805_HV]  (hidden comment: 08055A102FAT2A)
C10  ValueDisplayed: 10uF  VDC_V: 50V  [FP-GMC31X7R106K50NT_1206-MFG]  (hidden comment: GMC31X7R106K50NT)
C11  Cap_F: 100nF  VDC_V: 50V  [0603]  (hidden comment: C0603C104K5RACTU)
C12  Cap_F: 100nF  VDC_V: 50V  [FP-06035C104J4Z2A_0603-MFG]  (hidden comment: 06035C104J4Z2A)
C13  Cap_F: 100nF  VDC_V: 50V  [FP-06035C104J4Z2A_0603-MFG]  (hidden comment: 06035C104J4Z2A)
C14  ValueDisplayed: 10uF  VDC_V: 50V  [FP-GMC31X7R106K50NT_1206-MFG]  (hidden comment: GMC31X7R106K50NT)
C15  Cap_F: 100nF  VDC_V: 50V  [0603]  (hidden comment: C0603C104K5RACTU)
C16  VDC_V: 25V  ValueDisplayed: 10µF  [1206]  (hidden comment: GRM31CR71E106MA12L)
C17  Cap_F: 100nF  VDC_V: 50V  [0603]  (hidden comment: C0603C104K5RACTU)
C18  1uF  [CAPC3225X270X30LL30]
C19  VDC_V: 25V  ValueDisplayed: 10uF  [1210_220]  (hidden comment: GRM32DR71E106KA12L)
C20  ValueDisplayed: 10uF  VDC_V: 50V  [FP-GMC31X7R106K50NT_1206-MFG]  (hidden comment: GMC31X7R106K50NT)
C21  ValueDisplayed: 150uF  VDC_V: 20V  [FP-T521D157M020ATE050_2917-MFG]  (hidden comment: T521D157M020ATE050)
C22  ValueDisplayed: 10uF  VDC_V: 50V  [FP-GMC31X7R106K50NT_1206-MFG]  (hidden comment: GMC31X7R106K50NT)
C23  ValueDisplayed: 150uF  VDC_V: 20V  [FP-T521D157M020ATE050_2917-MFG]  (hidden comment: T521D157M020ATE050)
C24  VDC_V: 50V  ValueDisplayed: 1uF  [6032-28]  (hidden comment: 293D105X9050C2TE3)
C25  Cap_F: 100nF  VDC_V: 50V  [0603]  (hidden comment: C0603C104K5RACTU)
C26  Cap_F: 100nF  VDC_V: 50V  [0603]  (hidden comment: C0603C104K5RACTU)
C27  VDC_V: 25V  ValueDisplayed: 10uF  [1210_220]  (hidden comment: GRM32DR71E106KA12L)
C33  Cap_F: 100nF  VDC_V: 50V  [0603]  (hidden comment: C0603C104K5RACTU)
C34  VDC_V: 25V  ValueDisplayed: 10µF  [1206]  (hidden comment: GRM31CR71E106MA12L)
C79  VDC_V: 25V  ValueDisplayed: 10µF  [1206]  (hidden comment: GRM31CR71E106MA12L)
C112  VDC_V: 10V  ValueDisplayed: 68uF  [1206_190]  (hidden comment: C3216X5R1A686M160AC)
C128  VDC_V: 25V  ValueDisplayed: 10µF  [1206]  (hidden comment: GRM31CR71E106MA12L)
C139  VDC_V: 25V  ValueDisplayed: 1uF  [0603]  (hidden comment: C1608X5R1E105K080AC)
C140  VDC_V: 25V  ValueDisplayed: 1uF  [0603]  (hidden comment: C1608X5R1E105K080AC)
C141  VDC_V: 25V  ValueDisplayed: 1uF  [0603]  (hidden comment: C1608X5R1E105K080AC)
C142  VDC_V: 25V  ValueDisplayed: 1uF  [0603]  (hidden comment: C1608X5R1E105K080AC)
C143  VDC_V: 25V  ValueDisplayed: 1uF  [0603]  (hidden comment: C1608X5R1E105K080AC)
C144  VDC_V: 25V  ValueDisplayed: 1uF  [0603]  (hidden comment: C1608X5R1E105K080AC)
C145  VDC_V: 25V  ValueDisplayed: 1uF  [0603L]  (hidden comment: C1608X5R1E105K080AC)
C146  VDC_V: 25V  ValueDisplayed: 1uF  [0603]  (hidden comment: C1608X5R1E105K080AC)
C147  VDC_V: 25V  ValueDisplayed: 1uF  [0603]  (hidden comment: C1608X5R1E105K080AC)
C148  VDC_V: 25V  ValueDisplayed: 1uF  [0603L]  (hidden comment: C1608X5R1E105K080AC)
C149  VDC_V: 25V  ValueDisplayed: 1uF  [0603]  (hidden comment: C1608X5R1E105K080AC)
C150  VDC_V: 25V  ValueDisplayed: 1uF  [0603]  (hidden comment: C1608X5R1E105K080AC)
C160  VDC_V: 25V  ValueDisplayed: 1uF  [0603L]  (hidden comment: C1608X5R1E105K080AC)
C164  Cap_F: 1nF  VDC_V: 250V  [FP-GCJ21AR72E102KXJ1D_0805-MFG]  (hidden comment: GCJ21AR72E102KXJ1D)
J_1V85  SL 11 112 02G  [Fischer_SL-11-112-02G]
J_2V5  SL 11 112 02G  [Fischer_SL-11-112-02G]
J_3V3  SL 11 112 02G  [Fischer_SL-11-112-02G]
J_3V3_2  SL 11 112 02G  [Fischer_SL-11-112-02G]
J_5V  SL 11 112 02G  [Fischer_SL-11-112-02G]
J_LS  SL 11 112 02G  [Fischer_SL-11-112-02G]
Q36  SI2337DS-T1-E3  [SOT-23]
Q37  2N7002KW  [SOT-323]
Q41  2N7002KW  [SOT-323]
Q42  SI2337DS-T1-E3  [SOT-23]
R10  ValueDisplayed: 100k  [0805_HV]  (hidden comment: RG2012P-104-B-T5)
R11  ValueDisplayed: 2.61k  [0805_HV]  (hidden comment: RG2012P-2611-B-T5)
R12  ValueDisplayed: 1.00k  [0805_HV]  (hidden comment: RG2012P-102-B-T5)
R13  ValueDisplayed: 20.0k  [0805_HV]  (hidden comment: RT0805BRD0720KL)
R15  ValueDisplayed: 8.25k  [0805_HV]  (hidden comment: RT0805BRD078K25L)
R16  ValueDisplayed: 6.49k  [0805_HV]  (hidden comment: RT0805BRD076K49L)
R17  ValueDisplayed: 8.66k  [0805_HV]  (hidden comment: RT0805BRD078K66L)
R18  ValueDisplayed: 2.08k  [0805_HV]  (hidden comment: RT0805BRD072K08L)
R19  ValueDisplayed: 4.70k  [0805_HV]  (hidden comment: RG2012P-472-B-T5)
R20  ValueDisplayed: 16.0k  [0805_HV]  (hidden comment: RG2012P-163-B-T5)
R21  ValueDisplayed: 2.0k  [0805_HV]  (hidden comment: CRCW08052K00JNEA)
R23  ValueDisplayed: 9.31k  [0805_HV]  (hidden comment: RT0805BRD079K31L)
R139  ValueDisplayed: 20.0k  [0805_HV]  (hidden comment: RT0805DRE0720KL)
R143  ValueDisplayed: 30.0k  [0805_HV]  (hidden comment: RG2012P-303-B-T5)
Supply_Sel  SL 11 112 03G  [Fischer_SL-11-112-03G]
TP1  5000  [Keystone5000]
TP2  5001  [Keystone5001]
TP3  5001  [Keystone5001]
TP4  5001  [Keystone5001]
TP5  5001  [Keystone5001]
TP6  5001  [Keystone5001]
TP8  5001  [Keystone5001]
TP9  5001  [Keystone5001]
TP10  5001  [Keystone5001]
U3  PartNumber: TPS7H2211-SP  [HKR0016A_Custom_A]  (hidden comment: TPS7H2211HKR/EM)
U4  TPS7A4501HKU/EM  [HKU0010_CUSTOM_A]  (value not drawn)
U5  LM117QML-SP  [NDT0003A]
U6  TPS7A4501HKU/EM  [HKU0010_CUSTOM_A]  (value not drawn)
U7  PartNumber: LM4050QML-SP  [NAC0010A-IPC_C]  (hidden comment: LM4050WG2.5-MPR)
U26  TPS7A4501HKU/EM  [HKU0010_CUSTOM_A]  (value not drawn)

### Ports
2V5_EN (out), 3V3_EN (out), 12V_EN (out)

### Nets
1.89V: J_1V85.1
2.5Vref: C139.2 C140.2 C141.2 C142.2 C143.2 C144.2 C145.2 C146.2 C147.2 C148.2 C149.2 C150.2 C160.2 J_2V5.1
3.3V: J_3V3.2 Q42.2(S) R21.2
3.3V_2: J_3V3_2.2
5Vcc: C26.1 C79.1 J_5V.2 U6.1(~{SHDN}) U6.2(IN) U6.3(IN) U6.4(IN)
12V: C13.2 C14.2 C21.2(ANODE) C22.2 C34.1 R10.2 Supply_Sel.2 U3.1(VIN) U3.2(VIN) U3.3(VIN) U3.4(VIN) U26.1(~{SHDN}) U26.2(IN) U26.3(IN) U26.4(IN)
12Vcc: C16.1 C17.1 J_LS.2 Q36.2(S) R139.2 U4.1(~{SHDN}) U4.2(IN) U4.3(IN) U4.4(IN)
Batt_out: C24.1(+) U5.1(IN)
GND: 12V_Supply.2 C10.1 C12.1 C13.1 C14.1 C16.2 C17.2 C18.1 C19.2 C20.1 C21.1(CATHODE) C22.1 C23.1(CATHODE) C24.2(-) C26.2 C27.2 C34.2 C79.2 C112.2 C128.2 C139.1 C140.1 C141.1 C142.1 C143.1 C144.1 C145.1 C146.1 C147.1 C148.1 C149.1 C150.1 C160.1 Q37.2(S) Q41.2(S) R15.1 R16.1 R17.1 R19.1 R23.1 TP2.1 TP3.1 TP4.1 TP5.1 TP6.1 TP8.1 TP9.1 TP10.1 U3.5(NC) U3.8(GND) U3.9(NC) U3.10(NC) U3.11(NC) U3.17(Thermal_Pad) U4.5(NC) U4.10(GND) U4.11(PAD) U6.5(NC) U6.10(GND) U6.11(PAD) U26.5(NC) U26.10(GND) U26.11(PAD)
2V5_EN: Q37.1(G) Q41.1(G) ; port 2V5_EN
3V3_EN: C164.2 Q42.1(G) R21.1 ; port 3V3_EN
12V_EN: U3.6(EN) ; port 12V_EN
U5_ADJ: C15.2 R12.1 R17.2 U5.2(ADJ)
Net12V_Supply_1: 12V_Supply.1 Supply_Sel.3 TP1.1
NetC9_1: C9.1 C10.2 C12.2 C20.2 C23.2(ANODE) J_LS.1 U3.13(VOUT) U3.14(VOUT) U3.15(VOUT) U3.16(VOUT)
NetC9_2: C9.2 U3.12(SS)
NetC11_1: C11.1 C19.1 J_5V.1 R13.2 U4.6(OUT) U4.7(OUT) U4.8(OUT)
NetC11_2: C11.2 R13.1 R16.2 U4.9(SENSE/ADJ)
NetC15_1: C15.1 C18.2 R12.2 Supply_Sel.1 U5.3(OUT)
NetC25_1: C25.1 C27.1 J_1V85.2 R11.2 U6.6(OUT) U6.7(OUT) U6.8(OUT)
NetC25_2: C25.2 R11.1 R19.2 U6.9(SENSE/ADJ)
NetC33_1: C33.1 C128.1 J_3V3.1 R20.2 U26.6(OUT) U26.7(OUT) U26.8(OUT)
NetC33_2: C33.2 R20.1 R23.2 U26.9(SENSE/ADJ)
NetC112_1: C112.1 J_2V5.2 R18.1 U7.10(VREF)
NetC164_1: C164.1 J_3V3_2.1 Q42.3(D)
NetQ36_1: Q36.1(G) R139.1 R143.2
NetQ36_3: Q36.3(D) R18.2
NetQ37_3: Q37.3(D) R143.1
NetQ41_3: Q41.3(D) U7.1(GND/NC) U7.2(GND/NC) U7.3(GND/NC) U7.4(GND/NC) U7.5(GND) U7.6(GND/NC) U7.7(GND/NC) U7.8(GND/NC) U7.9(GND/NC)
NetR10_1: R10.1 R15.2 U3.7(OVP)

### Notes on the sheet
- LDO - 33.6V to 12V
  From top of stack to TPS7H5001-SP
- 12V to 5V LDO
  Vbais for the ADC128S103QML-SP
- 3V3 power for ADC128
- Power Sequencing:
  1- 3.3V for MCU
  2- 12V for INA1H94 -SP
  3- 5V for ADC128S102-SP & LMP7704-SP
  4- 3.3V for ADC128S102-SP & Temp Sensor Pull up
  5- 1.89V for TMP9R00-SP
  6- 2.5V turns on automatically

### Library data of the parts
12V_Supply = CMP-0074913-1: Terminal Block, 3.5mm Pitch, 2x1, TH; Manufacturer: On-Shore Technology; Cert_VDE: Y; CNHeader: False; Current_A: 6A; Green_Lifecycle: Active; Shrouded: N; Gender: Female; Green_REACh: Passed; Voltage_V: 150V; Row_Count: 1; Pitch_mm: 3.5; ContactFinish: Brass; CT: True
C9 = CMP-0007581-2: CAP, CERM, 1000 pF, 50 V, +/- 1%, C0G/NP0, 0805; Manufacturer: AVX; TaMin_C: -55°C; ESR_ohm: 0.112; Polarized: N; SizeAreaWB_mm2: 6.75; Value1: 0.112 ohm; U/M: EA; Value: 1000pF; TaMax_C: 125°C; SizeZ_mm: 1.45; SizeX_mm: 2; SizeY_mm: 1.25; Cap_Case: 0805; SizeArea_mm2: 2.5; Cap_F: 1nF; AEC Category: Q200
C10 C14 C20 C22 = CMP-0093201-1: 10 µF ±10% 50V Ceramic Capacitor X7R 1206 (3216 Metric); Manufacturer: Cal-Chip Electronics; AEC Qualified: No; SizeZ_mm: 1.8mm; TempCo: 15%; Value: 10µF
C11 C15 C17 C25 C26 C33 = CMP-0006861-3: CAP, CERM, 0.1 uF, 50 V, +/- 10%, X7R, 0603; Manufacturer: Kemet; TaMin_C: -55°C; Polarized: N; SizeAreaWB_mm2: 4.68; Value1: Unknown; U/M: EA; Value: 0.1uF; TaMax_C: 125°C; SizeZ_mm: 1; SizeX_mm: 1.6; SizeY_mm: 0.8; SizeArea_mm2: 1.28; AEC Category: Q200
C12 C13 = CMP-0094511-1: 0.1 µF ±5% 50V Ceramic Capacitor X7R 0603 (1608 Metric); Manufacturer: KYOCERA AVX; AEC Qualified: Yes; AEC Grade: NA; ValueDisplayed: 0.1uF; Value: 100nF; TempCo: 15%; SizeZ_mm: 0.9mm
C16 C34 C79 C128 = CMP-0082252-1: CAP, CERM, 10 µF, 25 V,+/- 20%, X7R, AEC-Q200 Grade 1, 1206; Manufacturer: MuRata; SizeAreaWB_mm2: 10.92; SizeArea_mm2: 5.12; AEC Qualified: Y; AEC Category: Q200; Value: 10uF; TaMax_C: 125°C; SizeZ_mm: 1.35; AEC Grade: 1; Polarized: N; TaMin_C: -55°C; SizeY_mm: 1.6; U/M: EA; SizeX_mm: 3.2
C18 = CMP-2000-06366-1: Chip Capacitor, 1 uF, +/- 10%, 100 V, -55 to 125 degC, 1210 (3225 Metric), RoHS, Tape and Reel GRM32ER72A105KA01L; Manufacturer: Murata; Temperature Coefficient: X7R; Product Training Modules: High-CapMultilayerCeramicCapacitors; Capacitance: 1µF; Catalog Drawings: GRMSeries_1210_2.5; Featured Product: GA3SafetyRecognizedCapsandHi-CapMLCC; Online Catalog: GRMSeries; Voltage - Rated: 100V; Other Names: 490-1857-6
C19 C27 = CMP-0009190-1: CAP, CERM, 10 uF, 25 V, +/- 10%, X7R, 1210; Manufacturer: MuRata; TaMin_C: -55°C; Polarized: N; SizeAreaWB_mm2: 14.7; Value1: Unknown; U/M: EA; Value: 10uF; TaMax_C: 125°C; SizeZ_mm: 2.2; SizeX_mm: 3.2; SizeY_mm: 2.5; Cap_Case: 1210; SizeArea_mm2: 8; Cap_F: 10µF; AEC Category: Q200
C21 C23 = CMP-0093169-1: 150µF Molded Tantalum Polymer Capacitor 20V 2917 (7343 Metric) 50mOhm @ 100kHz; Manufacturer: Kemet; IRMS_A: 2.1A; Leakage Current: 300uA; Dissipation Factor: 10%; SizeZ_mm: 3.1mm; AEC Qualified: No; Esr: 50m; Tolerance_%: 20%; Standoff Height: 0mm; Life: 2000Hours
C24 = CMP-0011596-1: CAP, TA, 1 uF, 50 V, +/- 10%, 4.6 ohm, SMD; Manufacturer: Vishay-Sprague; TaMin_C: -55°C; ESR_ohm: 4.6; Polarized: Y; SizeAreaWB_mm2: 41.6; Value1: 4.6 ohm; U/M: EA; Value: 1uF; TaMax_C: 125°C; SizeZ_mm: 2.8; SizeX_mm: 6; SizeY_mm: 3.2; Cap_Case: C; SizeArea_mm2: 19.2; CompType: Capacitor; Cap_F: 1µF; IRMS_A: 160mA; AEC Category: Q200
C112 = CMP-0008651-1: CAP, CERM, 68 uF, 10 V, +/- 20%, X5R, 1206_190; Manufacturer: TDK; TaMin_C: -55°C; ESR_ohm: 3.494m; Polarized: N; SizeAreaWB_mm2: 10.92; Value1: 0.003494 ohm; U/M: EA; Value: 68uF; TaMax_C: 85°C; SizeZ_mm: 1.9; SizeX_mm: 3.2; SizeY_mm: 1.6; SizeArea_mm2: 5.12; Cap_F: 68µF; IRMS_A: 3.8813A; AEC Category: Q200
C139-C144 C146 C147 C149 C150 = CMP-0007006-2: CAP, CERM, 1 uF, 25 V, +/- 10%, X5R, 0603; Manufacturer: TDK; TaMin_C: -55°C; Polarized: N; SizeAreaWB_mm2: 4.68; Value1: Unknown; U/M: EA; Value: 1uF; TaMax_C: 85°C; SizeZ_mm: 1; SizeX_mm: 1.6; SizeY_mm: 0.8; SizeArea_mm2: 1.28; Cap_F: 1µF; AEC Category: Q200
C145 C148 C160 = CMP-0007006-2: CAP, CERM, 1 uF, 25 V, +/- 10%, X5R, 0603; Manufacturer: TDK; TaMin_C: -55°C; Polarized: N; SizeAreaWB_mm2: 4.68; Value1: Unknown; U/M: EA; Value: 1uF; TaMax_C: 85°C; SizeZ_mm: 1; SizeX_mm: 1.6; SizeY_mm: 0.8; Cap_Case: 0603; SizeArea_mm2: 1.28; Cap_F: 1µF; AEC Category: Q200
C164 = CMP-0091091-1: Cap Ceramic 0.001uF 250V X7R 10% Pad SMD 0805 Soft Termination 125C Automotive T/R; Manufacturer: Murata; Value: 1nF; ValueDisplayed: 1000pF; AEC Qualified: Yes; AEC Grade: Grade 1; TempCo: 15%; SizeZ_mm: 1mm
J_1V85 J_2V5 J_3V3 J_3V3_2 J_5V J_LS = CMP-0075049-1: as J_pump on sheet Batt_Stack_Control (NMOS)
Q36 Q42 = CMP-0000095-3: MOSFET, P-CH, -80 V, -1.2 A, SOT-23; Alternate Manufacturer: None; Manufacturer: Vishay-Siliconix; VdsMax_V: -80V; AEC Category: Q101; Value: -80V; IdsMax_A: -1.2A; SizeX_mm: 2.5; SizeZ_mm: 1.1; Vgs_V: -20V; SizeY_mm: 3; SizeArea_mm2: 7.5; SizeAreaWB_mm2: 14; QgTyp_nC: 11; ChMode: Enhancement; ChType: P; Value2: 11 nC
Q37 Q41 = CMP-0000774-1: MOSFET, N-CH, 60 V, 0.31 A, SOT-323; Alternate Manufacturer: None; Manufacturer: Fairchild Semiconductor; SizeZ_mm: 1.1; ChType: N; Value1: 1; VdsMax_V: 60V; SizeX_mm: 2.2; Vgs_V: 2.1V; Value: 60V; Rdson45_ohm: 1.6; SizeArea_mm2: 4.84; AEC Category: Q101; IdsMax_A: 310mA; SizeAreaWB_mm2: 10.24; U/M: EA
R10 = CMP-0018857-1: RES, 100 k, 0.1%, 0.125 W, 0805; Manufacturer: Susumu Co Ltd; Power_W: 125mW; TempCo: 25 ppm/C; U/M: EA; Value: 100k; EIA_Code: E192; SizeX_mm: 2; SizeY_mm: 1.25; SizeZ_mm: 1.45; Value2: 0.125W; SizeArea_mm2: 2.5; VDC_V: 100V; AEC Category: Q200
R11 = CMP-0018936-1: RES, 2.61 k, 0.1%, 0.125 W, 0805; Manufacturer: Susumu Co Ltd; Power_W: 125mW; TempCo: 25 ppm/C; Value_Code: 2k61; U/M: EA; Value: 2.61k; EIA_Code: E192; SizeX_mm: 2; SizeY_mm: 1.25; SizeZ_mm: 1.45; Value2: 0.125W; SizeArea_mm2: 2.5; VDC_V: 100V; AEC Category: Q200
R12 = CMP-0018855-2: RES, 1.00 k, 0.1%, 0.125 W, 0805; Manufacturer: Susumu Co Ltd; Power_W: 125mW; TempCo: 25 ppm/C; Value_Code: 1k00; U/M: EA; Value: 1.00k; EIA_Code: E192; Res_ohm: 1k; SizeX_mm: 2; SizeY_mm: 1.25; SizeZ_mm: 1.45; Value2: 0.125W; SizeArea_mm2: 2.5; VDC_V: 100V; AEC Category: Q200
R13 = CMP-0019773-1: RES, 20.0 k, 0.1%, 0.125 W, 0805; Manufacturer: Yageo America; Power_W: 125mW; TempCo: 25 ppm/C; Value_Code: 20k0; U/M: EA; Value: 20.0k; EIA_Code: E192; Res_ohm: 20k; SizeX_mm: 2; SizeY_mm: 1.25; SizeZ_mm: 1.45; Value2: 0.125W; SizeArea_mm2: 2.5; VDC_V: 150V; AEC Category: Q200
R15 = CMP-0020383-2: RES, 8.25 k, 0.1%, 0.125 W, 0805; Manufacturer: Yageo America; Power_W: 125mW; TempCo: 25 ppm/C; Value_Code: 8k25; U/M: EA; Value: 8.25k; EIA_Code: E192; SizeX_mm: 2; SizeY_mm: 1.25; SizeZ_mm: 1.45; Value2: 0.125W; SizeArea_mm2: 2.5; VDC_V: 150V; AEC Category: Q200
R16 = CMP-0020279-2: RES, 6.49 k, 0.1%, 0.125 W, 0805; Manufacturer: Yageo America; Power_W: 125mW; TempCo: 25 ppm/C; Value_Code: 6k49; U/M: EA; Value: 6.49k; EIA_Code: E192; SizeX_mm: 2; SizeY_mm: 1.25; SizeZ_mm: 1.45; Value2: 0.125W; SizeArea_mm2: 2.5; VDC_V: 150V; AEC Category: Q200
R17 = CMP-0020387-2: RES, 8.66 k, 0.1%, 0.125 W, 0805; Manufacturer: Yageo America; Power_W: 125mW; TempCo: 25 ppm/C; Value_Code: 8k66; U/M: EA; Value: 8.66k; EIA_Code: E192; SizeX_mm: 2; SizeY_mm: 1.25; SizeZ_mm: 1.45; Value2: 0.125W; SizeArea_mm2: 2.5; VDC_V: 150V; AEC Category: Q200
R18 = CMP-0019900-1: RES, 2.08 k, 0.1%, 0.125 W, 0805; Manufacturer: Yageo America; Power_W: 125mW; TempCo: 25 ppm/C; Value_Code: 2k08; U/M: EA; Value: 2.08k; EIA_Code: E192; SizeX_mm: 2; SizeY_mm: 1.25; SizeZ_mm: 1.45; Value2: 0.125W; SizeArea_mm2: 2.5; VDC_V: 150V; AEC Category: Q200
R19 = CMP-0018992-2: RES, 4.70 k, 0.1%, 0.125 W, 0805; Manufacturer: Susumu Co Ltd; Power_W: 125mW; TempCo: 25 ppm/C; Value_Code: 4k70; U/M: EA; Value: 4.70k; EIA_Code: E192; Res_ohm: 4.7k; SizeX_mm: 2; SizeY_mm: 1.25; SizeZ_mm: 1.45; Value2: 0.125W; SizeArea_mm2: 2.5; VDC_V: 100V; AEC Category: Q200
R20 = CMP-0018896-1: RES, 16.0 k, 0.1%, 0.125 W, 0805; Manufacturer: Susumu Co Ltd; Power_W: 125mW; TempCo: 25 ppm/C; Value_Code: 16k0; U/M: EA; Value: 16.0k; EIA_Code: E192; Res_ohm: 16k; SizeX_mm: 2; SizeY_mm: 1.25; SizeZ_mm: 1.45; Value2: 0.125W; SizeArea_mm2: 2.5; VDC_V: 100V; AEC Category: Q200
R21 = CMP-0020510-3: RES, 2.0 k, 5%, 0.125 W, AEC-Q200 Grade 0, 0805; Manufacturer: Vishay-Dale; Power_W: 125mW; TempCo: 200 ppm/C; Value_Code: 2k00; Value: 2.0k; EIA_Code: E24; Res_ohm: 2k; SizeX_mm: 2; SizeY_mm: 1.25; SizeZ_mm: 1.45; Value2: 0.125W; SizeArea_mm2: 2.5; AEC Qualified: Y; VDC_V: 150V; AEC Category: Q200; AEC Grade: 0
R23 = CMP-0020426-1: RES, 9.31 k, 0.1%, 0.125 W, 0805; Manufacturer: Yageo America; Power_W: 125mW; TempCo: 25 ppm/C; Value_Code: 9k31; U/M: EA; Value: 9.31k; EIA_Code: E192; SizeX_mm: 2; SizeY_mm: 1.25; SizeZ_mm: 1.45; Value2: 0.125W; SizeArea_mm2: 2.5; VDC_V: 150V; AEC Category: Q200
R139 = CMP-0020433-1: RES, 20.0 k, 0.5%, 0.125 W, 0805; Manufacturer: Yageo America; Power_W: 125mW; TempCo: 50 ppm/C; Value_Code: 20k0; U/M: EA; Value: 20.0k; EIA_Code: E192; Res_ohm: 20k; SizeX_mm: 2; SizeY_mm: 1.25; SizeZ_mm: 1.45; Value2: 0.125W; SizeArea_mm2: 2.5; VDC_V: 150V; AEC Category: Q200
R143 = CMP-0018952-2: RES, 30.0 k, 0.1%, 0.125 W, 0805; Manufacturer: Susumu Co Ltd; Power_W: 125mW; TempCo: 25 ppm/C; Value_Code: 30k0; U/M: EA; Value: 30.0k; Res_ohm: 30k; SizeX_mm: 2; SizeY_mm: 1.25; SizeZ_mm: 1.45; Value2: 0.125W; SizeArea_mm2: 2.5; VDC_V: 100V; AEC Category: Q200
Supply_Sel = CMP-0075048-1: as J4 on sheet Batt_Stack_Control (NMOS)
TP1 = CMP-0055137-2: Test Point, Miniature, Red, TH; Manufacturer: Keystone Electronics; CNHeader: FALSE; Green_Lifecycle: Active; Green_REACh: Passed; ContactFinish: Silver; CT: TRUE
TP2-TP6 TP8-TP10 = CMP-0055138-2: Test Point, Miniature, Black, TH; Manufacturer: Keystone Electronics; CNHeader: FALSE; Green_Lifecycle: Active; Green_REACh: Passed; ContactFinish: Silver; CT: TRUE
U3 = CMP-0860518-2: Radiation Hardened 7-V, 6-A Load Switch, HKR0016A (CFP-16); Manufacturer: Texas Instruments; SizeAreaWB_mm2: 359.90292; SizeX_mm: 25.142; AEC Qualified: N; SizeArea_mm2: 283.09892; AEC Category: Q200; SizeZ_mm: 2.33; SizeY_mm: 11.26; CompType: IC
U4 U6 U26 = CMP-0067526-3: Wide Vin Low-Dropout Voltage Regulator, HKU0010A (CFP-10); Manufacturer: Texas Instruments; SizeZ_mm: 2.59; CompType: IC; AEC Category: Q200; AEC Qualified: N; Rating: Space
U5 = CMP-0062-00013-3: 3-Terminal Adjustable Regulator, 3-pin TO-39; Manufacturer: Texas Instruments; PackageTopMarking: NSZSSXXYYA 5962R99517*05VXA LM117HRLQV Q; PowerWise: N; CompType: LDO IC; High-Reliability: Y
U7 = CMP-0088839-1: Precision Micropower Shunt Voltage Reference; Manufacturer: Texas Instruments; AEC Qualified: No; Nominal Supply Current: 40.5uA; Output Voltage: 2.5V; TaMin_C: -55°C; Number Of Outputs: 1; Ciiva Ids: 8716774; TaMax_C: +125°C; Output Type: Fixed; Import Ts: 1521862633; Standoff Height: 0.1mm; SizeZ_mm: 2.33mm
